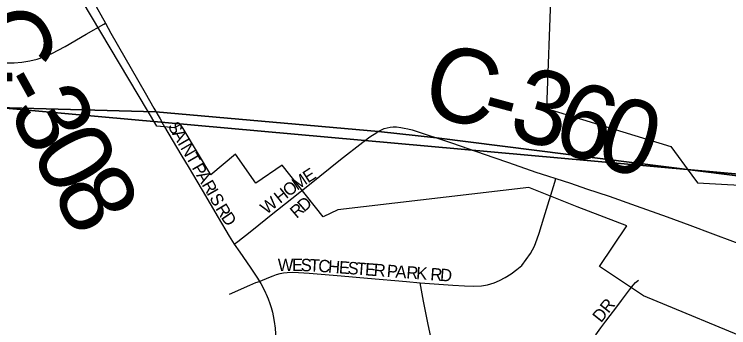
# Model space of a CAD drawing. Extents: x -209 to 4852, y 0 to 905.
# Drawn here: x 100.81 to 111.72, y 313.35 to 318.14 of the extents above; entities that cross this region are included whole.
import ezdxf

# ---------------------------------------------------------------- set-up
doc = ezdxf.new("R2010")
doc.units = 0
for name, color, linetype in [('GM_P_County_Alignment', 7, 'Continuous'), ('GM_X_Airport_Location_Class_2', 7, 'Continuous'), ('GM_X_Airport_Location_Class_3', 7, 'Continuous'), ('GM_X_County_Road_Text', 7, 'Continuous'), ('GM_X_Minor_Lake_Text', 7, 'Continuous'), ('GM_X_Minor_River', 7, 'Continuous'), ('GM_X_Township_Text', 7, 'Continuous'), ('GM_X_US_Location', 7, 'Continuous')]:
    doc.layers.add(name, color=color, linetype=linetype)

msp = doc.modelspace()

# ---------------------------------------------------------------- linework, layer by layer
at = {"layer": 'GM_X_Airport_Location_Class_2'}
for points in [[(99.581, 317.529), (99.747, 317.505), (100.437, 317.42), (100.683, 317.398), (100.807, 317.397), (100.926, 317.407), (101.045, 317.427), (101.161, 317.456), (101.275, 317.495), (101.386, 317.542), (101.587, 317.649), (101.909, 317.836), (102.18, 317.991), (102.201, 318.003)], [(103.107, 316.418), (103.288, 316.108), (103.367, 315.972), (103.465, 315.816), (103.681, 315.45), (103.925, 315.035), (104.095, 314.747), (104.171, 314.625)], [(108.796, 314.706), (108.829, 314.795), (108.901, 315.028), (109.066, 315.573), (109.083, 315.631)], [(104.171, 314.625), (104.223, 314.667), (104.412, 314.816), (104.786, 315.115), (104.833, 315.153), (105.174, 315.423), (105.221, 315.46)], [(107.011, 314.038), (107.507, 314.002), (107.688, 313.989), (107.826, 313.985), (107.945, 313.992), (108.04, 314.008), (108.143, 314.035), (108.224, 314.071), (108.31, 314.117), (108.402, 314.173), (108.489, 314.24), (108.561, 314.302), (108.632, 314.391), (108.696, 314.482), (108.757, 314.597), (108.796, 314.706)], [(104.171, 314.625), (104.253, 314.504), (104.356, 314.359), (104.424, 314.26), (104.526, 314.106), (104.556, 314.059)], [(104.556, 314.059), (104.566, 314.063), (104.698, 314.116), (104.763, 314.141), (104.818, 314.162), (104.871, 314.177), (104.924, 314.188), (104.976, 314.195), (105.067, 314.199), (105.153, 314.196), (105.315, 314.185), (105.438, 314.176), (105.802, 314.145), (106.205, 314.109), (106.8, 314.058), (107.011, 314.038)], [(104.556, 314.059), (104.575, 314.026), (104.617, 313.951), (104.65, 313.885), (104.66, 313.864), (104.688, 313.793), (104.715, 313.718), (104.734, 313.657), (104.753, 313.587), (104.763, 313.531), (104.779, 313.445), (104.794, 313.341), (104.801, 313.258), (104.802, 313.217), (104.802, 313.189), (104.803, 313.155), (104.792, 312.908), (104.77, 312.536), (104.718, 311.731), (104.708, 311.567)], [(107.227, 312.953), (107.199, 313.087), (107.127, 313.425), (107.06, 313.756), (107.018, 313.982), (107.011, 314.038)], [(109.58, 312.718), (109.587, 312.733), (109.591, 312.749), (109.594, 312.775), (109.595, 312.813), (109.595, 312.85), (109.598, 312.916), (109.603, 312.962), (109.61, 313.006), (109.618, 313.049), (109.631, 313.099), (109.644, 313.137), (109.657, 313.172), (109.694, 313.243), (109.769, 313.35), (109.844, 313.449), (109.915, 313.539), (109.997, 313.648)]]:
    msp.add_lwpolyline(points, dxfattribs=at)
at = {"layer": 'GM_X_County_Road_Text'}
for points in [[(101.69, 318.919), (101.755, 318.803), (102.013, 318.342), (102.201, 318.003)], [(102.201, 318.003), (102.284, 317.853), (102.808, 316.937), (102.941, 316.705), (103.037, 316.54), (103.086, 316.454), (103.107, 316.418)], [(105.221, 315.46), (105.318, 315.537), (105.792, 315.92), (106.133, 316.184), (106.243, 316.265), (106.346, 316.334), (106.351, 316.337), (106.376, 316.35), (106.389, 316.357), (106.401, 316.364), (106.46, 316.392), (106.508, 316.407), (106.553, 316.415), (106.6, 316.419), (106.648, 316.418), (106.714, 316.412), (106.765, 316.402), (106.822, 316.391), (106.888, 316.374), (106.965, 316.351), (107.135, 316.295), (107.26, 316.253), (107.488, 316.177), (108.137, 315.952), (108.36, 315.875), (108.776, 315.727), (108.954, 315.673), (109.083, 315.631)], [(109.083, 315.631), (109.305, 315.557), (109.551, 315.474), (109.895, 315.358), (110.31, 315.214), (110.785, 315.046), (111.132, 314.918), (111.483, 314.786), (111.779, 314.673), (112.069, 314.565), (112.194, 314.521), (112.265, 314.502), (112.335, 314.497), (112.405, 314.505), (112.464, 314.523), (112.502, 314.541)]]:
    msp.add_lwpolyline(points, dxfattribs=at)
at = {"layer": 'GM_X_Minor_Lake_Text'}
for points in [[(99.428, 316.745), (102.974, 316.648), (106.376, 316.35), (107.26, 316.253), (112.784, 315.555)], [(112.784, 315.555), (107.26, 316.253), (106.376, 316.35), (102.974, 316.648), (99.428, 316.745)]]:
    msp.add_lwpolyline(points, dxfattribs=at)
at = {"layer": 'GM_X_Minor_River'}
for points in [[(94.333, 337.437), (114.544, 335.599), (112.672, 315.623), (92.468, 317.445)], [(112.672, 315.623), (110.863, 295.32), (90.648, 297.385), (92.468, 317.445)]]:
    msp.add_lwpolyline(points, close=True, dxfattribs=at)
at = {"layer": 'GM_X_Township_Text'}
for points in [[(104.099, 313.865), (104.41, 314.003), (104.454, 314.022), (104.501, 314.039), (104.556, 314.059)], [(109.997, 313.648), (110.086, 313.766), (110.208, 313.931), (110.264, 314.003), (110.3, 314.043), (110.346, 314.079)]]:
    msp.add_lwpolyline(points, dxfattribs=at)
at = {"layer": 'GM_X_US_Location'}
for points in [[(112.17, 313.112), (110.424, 313.839), (109.752, 314.286), (110.166, 314.908), (109.409, 315.196), (108.67, 315.491), (105.755, 315.151), (105.529, 315.043), (104.903, 315.834), (104.5, 315.56), (104.19, 316.004), (103.81, 315.685), (103.389, 316.392), (103.35, 316.456), (103.257, 316.404), (102.988, 316.428), (100.99, 319.788)], [(109.004, 318.496), (108.941, 316.701), (110.839, 316.12), (111.158, 315.681), (111.245, 315.562), (112.258, 315.509)]]:
    msp.add_lwpolyline(points, dxfattribs=at)

# ---------------------------------------------------------------- texts
at = {"layer": 'GM_P_County_Alignment'}
for s, rotation, p in [('C', 299.0531, (100.026, 317.887)), ('C', 345.1796, (106.99, 316.643)), ('-', 299.0129, (100.479, 317.071)), ('3', 343.423, (108.323, 316.288)), ('3', 298.8767, (100.705, 316.664)), ('6', 341.8574, (108.981, 316.092)), ('-', 344.8786, (107.884, 316.406)), ('0', 340.6797, (109.635, 315.878)), ('0', 298.539, (101.042, 316.053)), ('8', 297.5356, (101.374, 315.442))]:
    msp.add_text(s, height=1.136, rotation=rotation, dxfattribs=at).set_placement(p)
at = {"layer": 'GM_X_Airport_Location_Class_3'}
for s, height, rotation, p in [('S', 0.189, 300.0499, (103.149, 316.431)), ('A', 0.189, 300.0609, (103.216, 316.315)), ('I', 0.189, 300.0752, (103.3, 316.171)), ('N', 0.189, 300.0566, (103.341, 316.099)), ('T', 0.189, 300.0532, (103.425, 315.955)), ('P', 0.189, 300.0499, (103.517, 315.796)), ('E', 0.189, 32.9174, (105.296, 315.555)), ('A', 0.189, 300.0609, (103.583, 315.68)), ('M', 0.189, 34.0639, (105.131, 315.443)), ('R', 0.189, 300.0642, (103.667, 315.536)), ('O', 0.189, 37.8405, (105.002, 315.343)), ('I', 0.189, 300.0268, (103.742, 315.406)), ('H', 0.189, 38.3703, (104.872, 315.24)), ('S', 0.189, 300.0532, (103.784, 315.334)), ('W', 0.189, 38.3763, (104.663, 315.074)), ('D', 0.189, 41.4113, (105.238, 315.111)), ('R', 0.189, 301.027, (103.877, 315.172)), ('R', 0.189, 40.6171, (105.122, 315.012)), ('D', 0.189, 304.3768, (103.961, 315.034)), ('W', 0.189, 359.9496, (104.835, 314.215)), ('E', 0.189, 359.9707, (105.052, 314.215)), ('S', 0.189, 359.235, (105.185, 314.215)), ('T', 0.189, 356.6384, (105.316, 314.213)), ('C', 0.189, 355.795, (105.448, 314.205)), ('H', 0.189, 355.7337, (105.598, 314.194)), ('E', 0.189, 355.7205, (105.764, 314.182)), ('S', 0.189, 355.7205, (105.897, 314.172)), ('T', 0.189, 355.7205, (106.03, 314.162)), ('E', 0.189, 355.7205, (106.163, 314.152)), ('R', 0.189, 355.724, (106.295, 314.142)), ('P', 0.189, 355.7348, (106.495, 314.127)), ('A', 0.189, 355.7365, (106.628, 314.117)), ('R', 0.189, 355.7346, (106.794, 314.105)), ('K', 0.189, 355.7337, (106.944, 314.094)), ('R', 0.189, 355.724, (107.16, 314.078)), ('D', 0.189, 355.7365, (107.309, 314.067)), ('DR', 0.1894, 51.3455, (109.773, 313.417))]:
    msp.add_text(s, height=height, rotation=rotation, dxfattribs=at).set_placement(p)

doc.saveas('drawing.dxf')
